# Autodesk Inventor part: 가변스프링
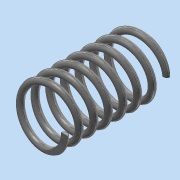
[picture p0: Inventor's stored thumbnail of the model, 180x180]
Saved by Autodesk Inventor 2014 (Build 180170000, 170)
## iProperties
Created: 2022-08
Part Number: 가변스프링
Material: 스테인레스 스틸
Document SubType Name: Modeling
Designer: dg
Density: 8.08 g/cm^3
Appearance: 반연마
Mass: 70.5056 g
Surface Area: 88.358 cm^2
Volume: 8.72595 cm^3
Author: dg
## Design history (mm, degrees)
sketch "스케치1"
  geometry: L1 (0, 0)-(16, 0); L2 (0, 0)-(0, 64); L3 (0, 64)-(16, 64); C1 r 2 at (16, 0)
  constraints: 6 end point, 1 centre point, 1 coincident, 1 horizontal, 1 parallel, 1 perpendicular, 1 vertical
  dimensions: "d0" = 4 diameter of C1; "d1" = 32 diameter of C1.centre L2; "d2" = 64 distance of L1.start L2.end (derived)
feature "코일1" pitch "d3" = 10; turns "d5" = 7; dims "d4" = 64 (= d2), "d6" = 0, angle "d7" = 90 deg, angle "d8" = 90 deg, "d9" = 0, "d10" = 0
node "작업 평면1"
node "작업 평면2"
feature "분할1"
feature "분할2"
node "솔리드1"
other parameters: "d11" = 90 deg
